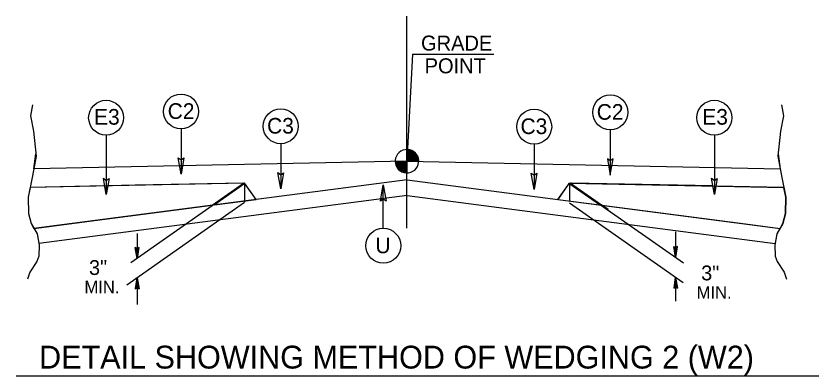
# Model space of a CAD drawing. Extents: x 1901670 to 1902225, y 193498 to 194278.
# Drawn here: x 1902034.84 to 1902069.97, y 194201.17 to 194216.92 of the extents above; entities that cross this region are included whole.
import ezdxf

# ---------------------------------------------------------------- set-up
doc = ezdxf.new("R2010")
doc.units = 0
for name, color, linetype in [('Old_Level_1', 7, 'Continuous'), ('Old_Level_11', 7, 'Continuous'), ('Old_Level_20', 7, 'Continuous'), ('Old_Level_21', 7, 'Continuous'), ('Old_Level_3', 7, 'Continuous'), ('Prop Shade Medium', 7, 'Continuous')]:
    doc.layers.add(name, color=color, linetype=linetype)

msp = doc.modelspace()

# ---------------------------------------------------------------- linework, layer by layer
at = {"layer": 'Old_Level_1'}
for p, q in [((1902051.947, 194207.637), (1902051.947, 194216.92)), ((1902051.947, 194210.568), (1902051.947, 194211.078)), ((1902051.435, 194210.568), (1902051.947, 194210.568)), ((1902051.944, 194210.056), (1902051.944, 194210.562)), ((1902051.947, 194210.568), (1902051.947, 194210.056)), ((1902052.459, 194210.568), (1902051.947, 194210.568)), ((1902051.947, 194210.056), (1902051.947, 194210.568)), ((1902044.845, 194209.611), (1902035.461, 194209.423)), ((1902044.845, 194209.611), (1902039.862, 194206.122)), ((1902045.355, 194208.894), (1902044.845, 194209.611)), ((1902044.845, 194209.611), (1902044.845, 194208.792)), ((1902058.541, 194208.896), (1902059.05, 194209.611)), ((1902059.05, 194209.611), (1902068.434, 194209.423)), ((1902059.05, 194209.611), (1902059.05, 194208.85)), ((1902059.05, 194209.611), (1902064.04, 194206.117)), ((1902044.841, 194208.767), (1902039.69, 194205.142)), ((1902059.05, 194208.751), (1902064.032, 194205.261)), ((1902040.143, 194207.403), (1902040.143, 194206.318)), ((1902063.702, 194207.482), (1902063.702, 194206.354)), ((1902040.143, 194206.318), (1902040.058, 194206.795)), ((1902040.143, 194206.734), (1902040.058, 194206.795)), ((1902040.143, 194206.318), (1902040.07, 194206.787)), ((1902040.083, 194206.777), (1902040.143, 194206.318)), ((1902040.143, 194206.318), (1902040.095, 194206.769)), ((1902040.107, 194206.76), (1902040.143, 194206.318)), ((1902040.143, 194206.318), (1902040.119, 194206.752)), ((1902040.131, 194206.743), (1902040.143, 194206.318)), ((1902040.143, 194206.318), (1902040.227, 194206.795)), ((1902040.227, 194206.795), (1902040.143, 194206.734)), ((1902040.215, 194206.787), (1902040.143, 194206.318)), ((1902040.143, 194206.318), (1902040.203, 194206.777)), ((1902040.191, 194206.769), (1902040.143, 194206.318)), ((1902040.143, 194206.318), (1902040.178, 194206.76)), ((1902040.167, 194206.752), (1902040.143, 194206.318)), ((1902040.143, 194206.318), (1902040.155, 194206.743)), ((1902040.143, 194206.734), (1902040.143, 194206.318)), ((1902063.702, 194206.354), (1902063.618, 194206.831)), ((1902063.702, 194206.769), (1902063.618, 194206.831)), ((1902063.702, 194206.354), (1902063.63, 194206.822)), ((1902063.642, 194206.813), (1902063.702, 194206.354)), ((1902063.702, 194206.354), (1902063.654, 194206.805)), ((1902063.666, 194206.795), (1902063.702, 194206.354)), ((1902063.702, 194206.354), (1902063.678, 194206.787)), ((1902063.69, 194206.777), (1902063.702, 194206.354)), ((1902063.702, 194206.354), (1902063.786, 194206.831)), ((1902063.786, 194206.831), (1902063.702, 194206.769)), ((1902063.774, 194206.822), (1902063.702, 194206.354)), ((1902063.702, 194206.354), (1902063.762, 194206.813)), ((1902063.75, 194206.805), (1902063.702, 194206.354)), ((1902063.702, 194206.354), (1902063.738, 194206.795)), ((1902063.726, 194206.787), (1902063.702, 194206.354)), ((1902063.702, 194206.354), (1902063.714, 194206.777)), ((1902063.702, 194206.769), (1902063.702, 194206.354)), ((1902040.143, 194205.46), (1902040.058, 194204.982)), ((1902040.071, 194204.991), (1902040.143, 194205.46)), ((1902040.143, 194205.46), (1902040.083, 194205)), ((1902040.095, 194205.009), (1902040.143, 194205.46)), ((1902040.143, 194205.46), (1902040.107, 194205.018)), ((1902040.119, 194205.026), (1902040.143, 194205.46)), ((1902040.143, 194205.46), (1902040.131, 194205.035)), ((1902040.143, 194205.46), (1902040.143, 194204.299)), ((1902040.143, 194205.46), (1902040.227, 194204.982)), ((1902040.143, 194205.044), (1902040.143, 194205.46)), ((1902040.155, 194205.035), (1902040.143, 194205.46)), ((1902040.143, 194205.46), (1902040.167, 194205.026)), ((1902040.179, 194205.018), (1902040.143, 194205.46)), ((1902040.143, 194205.46), (1902040.191, 194205.009)), ((1902040.203, 194205), (1902040.143, 194205.46)), ((1902040.143, 194205.46), (1902040.215, 194204.991)), ((1902063.702, 194205.493), (1902063.618, 194205.015)), ((1902063.63, 194205.024), (1902063.702, 194205.493)), ((1902063.702, 194205.493), (1902063.642, 194205.033)), ((1902063.654, 194205.042), (1902063.702, 194205.493)), ((1902063.702, 194205.493), (1902063.666, 194205.051)), ((1902063.678, 194205.06), (1902063.702, 194205.493)), ((1902063.702, 194205.493), (1902063.69, 194205.068)), ((1902063.702, 194205.493), (1902063.702, 194204.445)), ((1902063.702, 194205.493), (1902063.786, 194205.015)), ((1902063.702, 194205.078), (1902063.702, 194205.493)), ((1902063.714, 194205.068), (1902063.702, 194205.493)), ((1902063.702, 194205.493), (1902063.726, 194205.06)), ((1902063.738, 194205.051), (1902063.702, 194205.493)), ((1902063.702, 194205.493), (1902063.75, 194205.042)), ((1902063.762, 194205.033), (1902063.702, 194205.493)), ((1902063.702, 194205.493), (1902063.774, 194205.024)), ((1902040.058, 194204.982), (1902040.143, 194205.044)), ((1902040.143, 194205.044), (1902040.227, 194204.982)), ((1902063.618, 194205.015), (1902063.702, 194205.078)), ((1902063.702, 194205.078), (1902063.786, 194205.015))]:
    msp.add_line(p, q, dxfattribs=at)
for points in [[(1902035.56, 194213.036), (1902035.474, 194212.56), (1902035.604, 194211.884), (1902035.719, 194210.79), (1902035.56, 194209.925), (1902035.373, 194208.989), (1902035.388, 194208.283), (1902035.503, 194207.837), (1902035.763, 194207.39), (1902035.849, 194206.901), (1902035.834, 194206.411), (1902035.748, 194206.18), (1902035.446, 194205.72), (1902035.345, 194205.403)], [(1902068.334, 194213.036), (1902068.421, 194212.56), (1902068.291, 194211.884), (1902068.176, 194210.79), (1902068.334, 194209.925), (1902068.522, 194208.989), (1902068.507, 194208.283), (1902068.392, 194207.837), (1902068.132, 194207.39), (1902068.047, 194206.901), (1902068.06, 194206.411), (1902068.147, 194206.18), (1902068.449, 194205.72), (1902068.55, 194205.403)], [(1902051.952, 194211.078), (1902051.952, 194211.078), (1902051.952, 194210.568)], [(1902051.962, 194211.078), (1902051.962, 194210.568)], [(1902051.973, 194211.078), (1902051.973, 194210.568)], [(1902051.983, 194211.078), (1902051.983, 194210.568)], [(1902051.993, 194211.077), (1902051.993, 194210.568)], [(1902052.003, 194211.076), (1902052.003, 194210.568)], [(1902052.014, 194211.075), (1902052.014, 194210.568)], [(1902052.023, 194211.073), (1902052.023, 194210.568)], [(1902052.034, 194211.071), (1902052.034, 194210.568)], [(1902052.044, 194211.069), (1902052.044, 194210.568)], [(1902052.054, 194211.068), (1902052.054, 194210.568)], [(1902052.065, 194211.065), (1902052.065, 194210.568)], [(1902052.075, 194211.063), (1902052.075, 194210.568)], [(1902052.085, 194211.06), (1902052.085, 194210.568)], [(1902052.095, 194211.057), (1902052.095, 194210.568)], [(1902052.105, 194211.054), (1902052.105, 194210.568)], [(1902052.116, 194211.05), (1902052.116, 194210.568)], [(1902052.126, 194211.047), (1902052.126, 194210.568)], [(1902052.136, 194211.043), (1902052.136, 194210.568)], [(1902052.147, 194211.039), (1902052.146, 194210.568)], [(1902052.157, 194211.034), (1902052.157, 194210.568)], [(1902052.167, 194211.03), (1902052.167, 194210.568)], [(1902052.177, 194211.025), (1902052.177, 194210.568)], [(1902052.187, 194211.019), (1902052.187, 194210.568)], [(1902052.197, 194211.013), (1902052.197, 194210.568)], [(1902052.208, 194211.007), (1902052.208, 194210.568)], [(1902052.218, 194211.001), (1902052.218, 194210.568)], [(1902052.228, 194210.995), (1902052.228, 194210.568)], [(1902052.238, 194210.988), (1902052.238, 194210.568)], [(1902052.248, 194210.98), (1902052.248, 194210.568)], [(1902052.259, 194210.973), (1902052.259, 194210.568)], [(1902052.269, 194210.965), (1902052.269, 194210.568)], [(1902052.28, 194210.956), (1902052.28, 194210.568)], [(1902052.29, 194210.947), (1902052.289, 194210.567)], [(1902052.3, 194210.938), (1902052.3, 194210.568)], [(1902052.31, 194210.928), (1902052.31, 194210.567)], [(1902052.32, 194210.917), (1902052.32, 194210.567)], [(1902052.331, 194210.905), (1902052.331, 194210.568)], [(1902052.341, 194210.894), (1902052.341, 194210.567)], [(1902052.352, 194210.881), (1902052.352, 194210.567)], [(1902052.362, 194210.868), (1902052.361, 194210.568)], [(1902052.372, 194210.854), (1902052.372, 194210.567)], [(1902052.381, 194210.837), (1902052.381, 194210.567)], [(1902052.391, 194210.82), (1902052.391, 194210.568)], [(1902051.438, 194210.568), (1902051.438, 194210.512)], [(1902051.449, 194210.568), (1902051.449, 194210.452)], [(1902051.459, 194210.568), (1902051.459, 194210.415)], [(1902051.47, 194210.568), (1902051.47, 194210.385)], [(1902051.479, 194210.568), (1902051.479, 194210.36)], [(1902051.489, 194210.568), (1902051.489, 194210.338)], [(1902051.499, 194210.568), (1902051.499, 194210.32)], [(1902051.51, 194210.568), (1902051.51, 194210.301)], [(1902051.52, 194210.568), (1902051.52, 194210.286)], [(1902051.531, 194210.568), (1902051.531, 194210.27)], [(1902051.541, 194210.568), (1902051.541, 194210.257)], [(1902051.551, 194210.568), (1902051.551, 194210.244)], [(1902051.561, 194210.568), (1902051.561, 194210.231)], [(1902051.571, 194210.568), (1902051.571, 194210.22)], [(1902051.582, 194210.568), (1902051.582, 194210.21)], [(1902051.592, 194210.568), (1902051.592, 194210.2)], [(1902051.603, 194210.568), (1902051.603, 194210.189)], [(1902051.613, 194210.568), (1902051.612, 194210.181)], [(1902051.622, 194210.568), (1902051.622, 194210.171)], [(1902051.632, 194210.568), (1902051.632, 194210.164)], [(1902051.643, 194210.568), (1902051.643, 194210.156)], [(1902051.653, 194210.568), (1902051.653, 194210.149)], [(1902051.663, 194210.568), (1902051.663, 194210.142)], [(1902051.674, 194210.568), (1902051.674, 194210.135)], [(1902051.684, 194210.568), (1902051.684, 194210.128)], [(1902051.694, 194210.568), (1902051.694, 194210.122)], [(1902051.704, 194210.568), (1902051.704, 194210.117)], [(1902051.714, 194210.568), (1902051.714, 194210.112)], [(1902051.725, 194210.568), (1902051.725, 194210.106)], [(1902051.735, 194210.568), (1902051.735, 194210.102)], [(1902051.746, 194210.568), (1902051.746, 194210.097)], [(1902051.756, 194210.568), (1902051.755, 194210.093)], [(1902051.765, 194210.568), (1902051.765, 194210.09)], [(1902051.776, 194210.568), (1902051.776, 194210.085)], [(1902051.786, 194210.568), (1902051.786, 194210.082)], [(1902051.796, 194210.568), (1902051.796, 194210.079)], [(1902051.807, 194210.568), (1902051.807, 194210.076)], [(1902051.817, 194210.568), (1902051.817, 194210.073)], [(1902051.828, 194210.568), (1902051.827, 194210.07)], [(1902051.837, 194210.568), (1902051.837, 194210.068)], [(1902051.848, 194210.568), (1902051.847, 194210.066)], [(1902051.857, 194210.568), (1902051.857, 194210.064)], [(1902051.868, 194210.568), (1902051.868, 194210.063)], [(1902051.878, 194210.568), (1902051.878, 194210.06)], [(1902051.889, 194210.568), (1902051.889, 194210.06)], [(1902051.899, 194210.568), (1902051.898, 194210.058)], [(1902051.909, 194210.568), (1902051.909, 194210.057)], [(1902051.919, 194210.568), (1902051.919, 194210.057)], [(1902051.929, 194210.568), (1902051.929, 194210.057)], [(1902051.94, 194210.568), (1902051.94, 194210.056), (1902051.94, 194210.056)], [(1902052.402, 194210.801), (1902052.402, 194210.567)], [(1902052.413, 194210.779), (1902052.413, 194210.567)], [(1902052.423, 194210.756), (1902052.423, 194210.568)], [(1902052.433, 194210.727), (1902052.433, 194210.567)], [(1902052.443, 194210.692), (1902052.443, 194210.567)], [(1902052.453, 194210.64), (1902052.453, 194210.568)]]:
    msp.add_lwpolyline(points, dxfattribs=at)
for start, end in [(358.0003, 356.1713), (359.9905, 89.9905), (179.9905, 268.7186), (269.6533, 269.9905)]:
    msp.add_arc((1902051.947, 194210.567), 0.512, start, end, dxfattribs=at)
at = {"layer": 'Old_Level_11'}
for p, q in [((1902042.062, 194211.978), (1902042.062, 194210)), ((1902060.842, 194211.941), (1902060.842, 194209.963)), ((1902038.792, 194211.703), (1902038.792, 194209.108)), ((1902065.401, 194211.703), (1902065.401, 194209.108)), ((1902046.423, 194211.334), (1902046.423, 194209.356)), ((1902057.512, 194211.314), (1902057.512, 194209.336)), ((1902035.619, 194210.241), (1902035.712, 194210.893)), ((1902068.184, 194210.893), (1902068.277, 194210.241)), ((1902051.947, 194210.567), (1902035.619, 194210.241)), ((1902051.947, 194210.568), (1902068.277, 194210.241)), ((1902051.954, 194209.753), (1902035.625, 194207.627)), ((1902050.909, 194207.635), (1902050.909, 194209.528)), ((1902051.954, 194209.753), (1902068.271, 194207.629)), ((1902051.948, 194209.064), (1902035.837, 194206.966)), ((1902051.948, 194209.064), (1902068.058, 194206.967)), ((1902034.843, 194201.171), (1902069.971, 194201.171))]:
    msp.add_line(p, q, dxfattribs=at)
for points in [[(1902042.185, 194210.709), (1902042.062, 194210), (1902041.936, 194210.713), (1902042.062, 194210.622)], [(1902060.72, 194210.671), (1902060.842, 194209.963), (1902060.968, 194210.675), (1902060.842, 194210.585)], [(1902038.914, 194209.817), (1902038.792, 194209.108), (1902038.666, 194209.82), (1902038.792, 194209.73)], [(1902046.546, 194210.065), (1902046.423, 194209.356), (1902046.297, 194210.069), (1902046.423, 194209.978)], [(1902057.634, 194210.045), (1902057.512, 194209.336), (1902057.386, 194210.049), (1902057.512, 194209.958)], [(1902065.523, 194209.817), (1902065.401, 194209.108), (1902065.275, 194209.82), (1902065.401, 194209.73)], [(1902050.786, 194208.819), (1902050.909, 194209.528), (1902051.035, 194208.816), (1902050.909, 194208.906)]]:
    msp.add_lwpolyline(points, close=True, dxfattribs=at)
for centre in [(1902042.063, 194212.744), (1902060.842, 194212.706), (1902038.784, 194212.469), (1902065.394, 194212.469), (1902046.424, 194212.1), (1902057.512, 194212.079), (1902050.909, 194206.869)]:
    msp.add_circle(centre, 0.765, dxfattribs=at)
at = {"layer": 'Old_Level_3'}
for q in [(1902051.945, 194210.568), (1902055.752, 194215.251)]:
    msp.add_line((1902052.195, 194215.251), q, dxfattribs=at)
at = {"layer": 'Prop Shade Medium'}
for p, q in [((1902035.461, 194209.423), (1902035.373, 194208.989)), ((1902038.725, 194209.489), (1902035.461, 194209.423)), ((1902044.799, 194209.61), (1902040.048, 194209.515)), ((1902043.416, 194208.642), (1902044.799, 194209.61)), ((1902059.152, 194209.61), (1902059.096, 194209.61)), ((1902059.096, 194209.61), (1902060.746, 194208.455)), ((1902065.335, 194209.485), (1902059.152, 194209.61)), ((1902068.434, 194209.423), (1902065.466, 194209.482)), ((1902038.053, 194207.943), (1902043.416, 194208.642)), ((1902060.746, 194208.455), (1902060.476, 194208.644)), ((1902060.476, 194208.644), (1902066.754, 194207.827)), ((1902060.746, 194208.455), (1902060.746, 194208.455)), ((1902060.746, 194208.455), (1902060.746, 194208.455)), ((1902060.746, 194208.455), (1902060.746, 194208.455)), ((1902060.746, 194208.455), (1902060.746, 194208.455)), ((1902060.746, 194208.455), (1902060.746, 194208.455)), ((1902066.754, 194207.827), (1902068.271, 194207.629)), ((1902066.754, 194207.827), (1902066.754, 194207.827))]:
    msp.add_line(p, q, dxfattribs=at)
for points in [[(1902040.048, 194209.515), (1902038.858, 194209.491), (1902038.792, 194209.108), (1902038.725, 194209.489)], [(1902065.466, 194209.482), (1902065.401, 194209.108), (1902065.335, 194209.485)], [(1902068.271, 194207.629), (1902068.392, 194207.837), (1902068.507, 194208.283), (1902068.522, 194208.989), (1902068.434, 194209.423)], [(1902035.373, 194208.989), (1902035.388, 194208.283), (1902035.503, 194207.837)], [(1902035.503, 194207.837), (1902035.625, 194207.627), (1902038.053, 194207.943)]]:
    msp.add_lwpolyline(points, dxfattribs=at)
for points in [[(1902045.355, 194208.894), (1902044.859, 194209.59), (1902043.524, 194208.656)], [(1902059.035, 194209.591), (1902058.541, 194208.896), (1902060.367, 194208.658)]]:
    msp.add_lwpolyline(points, close=True, dxfattribs=at)

# ---------------------------------------------------------------- texts
at = {"layer": 'Old_Level_11'}
for s, p in [('GRADE', (1902052.561, 194215.409)), ('POINT', (1902052.719, 194214.415))]:
    msp.add_text(s, height=0.656, dxfattribs=at).set_placement(p)
at = {"layer": 'Old_Level_20'}
for s, height, p in [('C2', 0.6851, (1902041.477, 194212.42)), ('C2', 0.6851, (1902060.249, 194212.383)), ('E3', 0.6851, (1902038.258, 194212.167)), ('E3', 0.6851, (1902064.868, 194212.167)), ('C3', 0.6851, (1902045.826, 194211.776)), ('C3', 0.6851, (1902056.914, 194211.756)), ('U', 0.685, (1902050.566, 194206.54)), ('3"', 0.6491, (1902038.035, 194205.59)), ('3"', 0.6491, (1902064.82, 194205.355))]:
    msp.add_text(s, height=height, dxfattribs=at).set_placement(p)
at = {"layer": 'Old_Level_21'}
for s, height, p in [('MIN.', 0.5424, (1902037.836, 194204.792)), ('MIN.', 0.5424, (1902064.621, 194204.557)), ('DETAIL SHOWING METHOD OF WEDGING 2 (W2)', 1, (1902035.85, 194201.495))]:
    msp.add_text(s, height=height, dxfattribs=at).set_placement(p)

doc.saveas('drawing.dxf')
